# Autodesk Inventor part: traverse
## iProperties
Shininess: 64.0
Length Units: 11269
Angle Units: 11279
Time Units: 11290
Mass Units: 11283
Length Display Precision: 3
Angle Display Precision: 2
Compacted: True
Part Number: traverse
Document SubType Name: Modeling
Created: 2004-12
Material: Par défaut
Designer: LEGERET Philippe
Density: 0.0
Volumn: 0.0
Area: 0.0
PropertySet Name: Model Information
Control State: 0
Master: False
Checked Out: False
Author: LEGERET Philippe
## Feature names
1. Extrusion1
2. Extrusion2
3. Chanfrein1 [Chamfer]
